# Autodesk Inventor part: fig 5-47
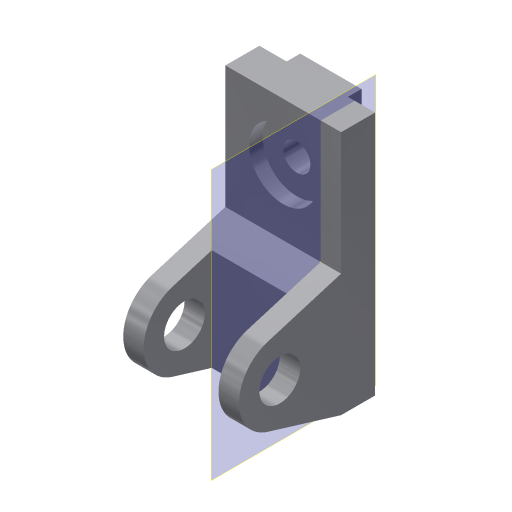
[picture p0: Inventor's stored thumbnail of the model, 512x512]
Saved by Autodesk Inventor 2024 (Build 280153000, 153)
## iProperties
Shininess: 65.0
Angle Display Precision: 2
Document Length Units: 11269
Document Angle Units: 11279
Document Time Units: 11290
Document Mass Units: 11283
Document Length Units Precision: 3
Document Angle Units Precision: 2
Created: 2001-11
Part Number: fig 5-47
Document SubType Name: Modeling
Designer: Renu Muthoo
Density: 1 g/cm^3
Material: Generic
Appearance: Aluminum - Flat
Density: 0.0
Volumn: 0.0
Area: 0.0
PropertySet Name: Model Information
Control State: 0
Master: False
Checked Out: False
Author: Renu Muthoo
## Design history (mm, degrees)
sketch "Sketch2"
  geometry: L1 (33.257, 104.664)-(33.257, -75.336); L2 (33.257, -75.336)-(8.257, -75.336); L3 (8.257, -75.336)-(-45.451, -59.045); L4 (-45.451, -1.628)-(8.257, 14.664); L5 (8.257, 14.664)-(8.257, 104.664); L6 (8.257, 104.664)-(33.257, 104.664); C1 r 15 at (-36.743, -30.336); A1 r 30 centre (-36.743, -30.336) between (-45.451, -1.628) and (-45.451, -59.045)
  constraints: 12 end point, 2 centre point, 2 equal length, 2 parallel, 2 point on circle, 2 tangent, 1 coincident, 1 perpendicular, 1 vertical
  dimensions: "d0" = 180 distance of L1.start L1.end; "d1" = 30 radius of A1; "d2" = 25 distance of L5.end L1.start; "d3" = 45 distance from line of L2 A1.centre; "d4" = 70 distance from line of L1 A1.centre; "d5" = 30 diameter of C1
extrude "Extrusion1" new body sketch "Sketch2" distance "d6" = 85; taper "d7" = 0 deg
workplane "Work Plane1"
sketch "Sketch3"
  geometry: L1 (15, 62.364)-(70, 62.364); L2 (70, 62.364)-(70, -52.386); L3 (70, -52.386)-(15, -52.386); L4 (15, -52.386)-(15, 62.364); L5 (0, -45)-(0, -28.708) reference
  constraints: 8 end point, 2 parallel, 1 horizontal, 1 perpendicular
  dimensions: "d8" = 55 distance of L1.start L1.end; "d9" = 15 distance between parallel lines of L5 L4
extrude "Extrusion2" cut sketch "Sketch3" distance "d10" = 50; taper "d11" = 0 deg
sketch "Sketch4"
  geometry: L1 (0, 25)-(85, 25) reference; L2 (0, 0)-(0, 25) reference; L3 (20, 25)-(65, 25); L4 (65, 25)-(65, 35); L5 (65, 35)-(20, 35); L6 (20, 35)-(20, 25)
  constraints: 8 end point, 2 parallel, 1 horizontal, 1 perpendicular, 1 point on line
  dimensions: "d12" = 45 distance of L4.end L5.end; "d13" = 10 distance of L3.end L4.end; "d14" = 20 distance between parallel lines of L2 L6
extrude "Extrusion3" join sketch "Sketch4" stored distance "d15" = 50; taper "d16" = 0 deg
sketch "Sketch5"
  geometry: L1 (85, 0)-(85, 90) reference; L2 (0, 90)-(85, 90) reference; 1 further point
  dimensions: "d17" = 42 distance from line of L2 point (42.5, 48); "d18" = 42.5 distance from line of L1 point (42.5, 48)
hole "Hole1" sketch "Sketch5" diameter "d19" = 20; stored, may be unused: countersink angle "d23" = 82 deg, drill point angle "d25" = 118 deg; dims "d20" = 6, "d21" = 50, "d22" = 10, "d24" = 8
workplane "Work Plane7"
workpoint "Work Point7"
workpoint "Work Point8"
body "Solid1"
node "Sketch1"
other parameters: "d29" = 0
